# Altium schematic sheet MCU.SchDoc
size A4
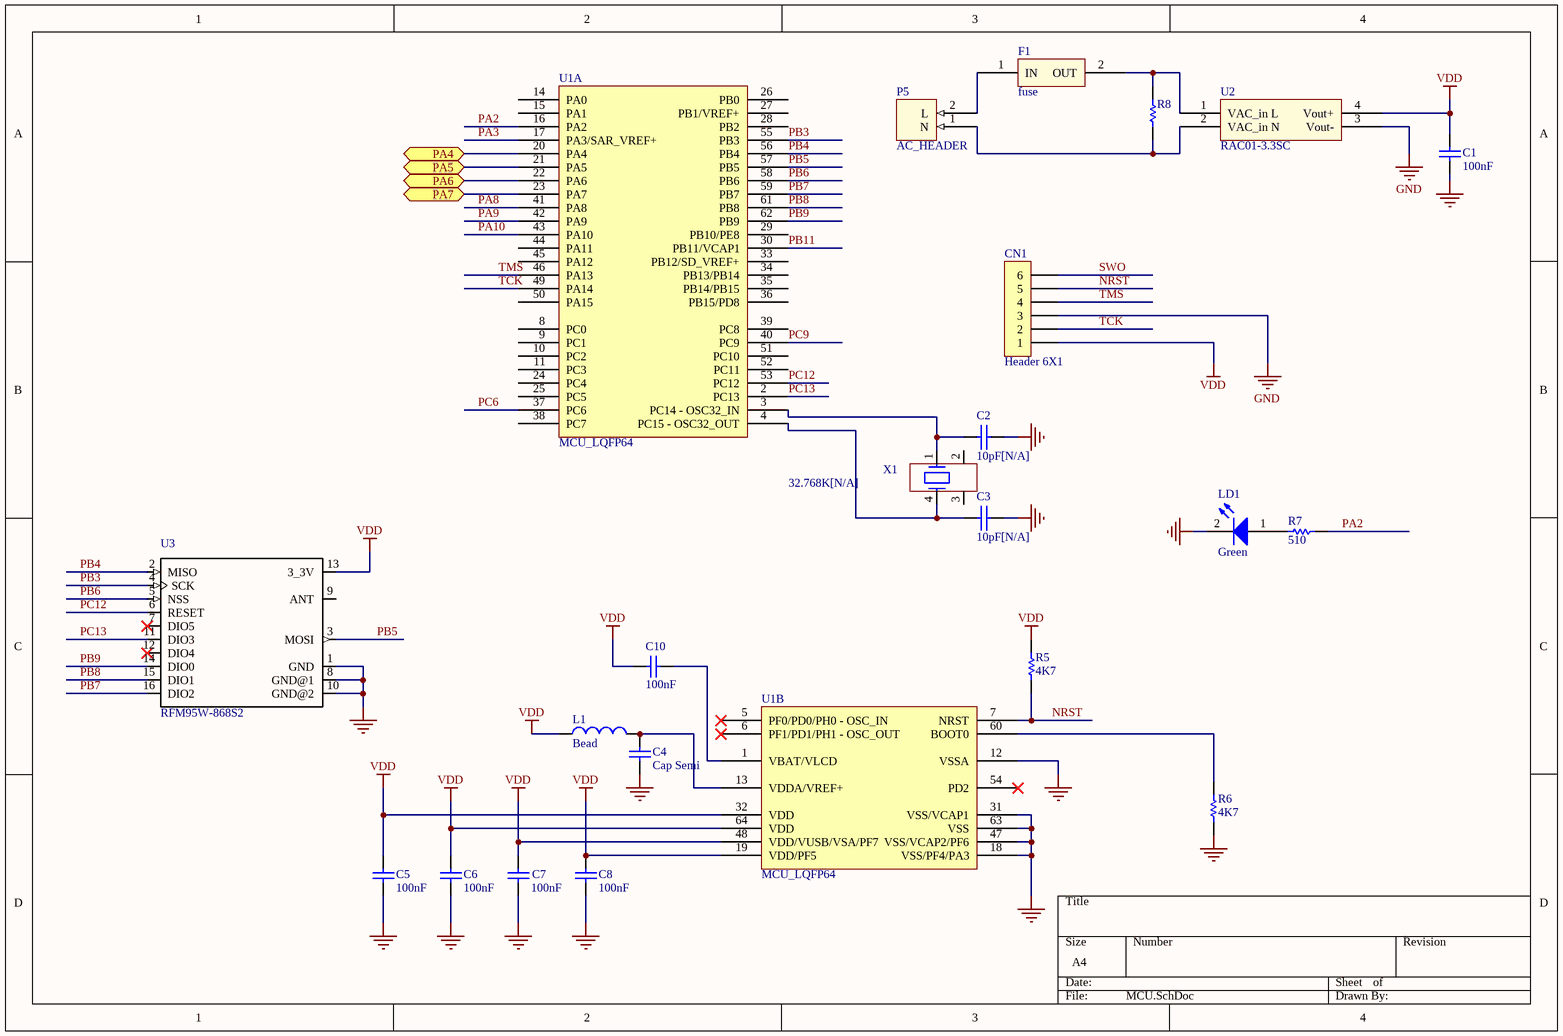
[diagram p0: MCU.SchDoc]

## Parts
C1  100nF  [0603C]
C2  10pF[N/A]  [0603C]
C3  10pF[N/A]  [0603C]
C4  Cap Semi  [1608[0603]]
C5  100nF  [0603C]
C6  100nF  [0603C]
C7  100nF  [0603C]
C8  100nF  [0603C]
C10  100nF  [0603C]
CN1  Header 6X1  [1*6P]
F1  fuse  [fuse]
L1  Bead  [INDC1608L]
LD1  Green  [0603D]
P5  AC_HEADER  [ac_header_2]
R5  4K7  [0603R]
R6  4K7  [0603R]
R7  510  [0603R]
R8  (no value)  [varistor]
U1  MCU_LQFP64  [LQFP64]  (parts A,B of 2)
U2  RAC01-3.3SC  [RAC01-3.3SC]
U3  RFM95W-868S2  [XCVR_RFM95W-868S2]
X1  32.768K[N/A]  [XTAL_4SM_8X3R8]

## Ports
PA4, PA5, PA6, PA7

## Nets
GND: C1.2 C2.2 C3.2 C4.2 C5.2 C6.2 C7.2 C8.2 CN1.3 LD1.2(K) R6.1 U1.12(VSSA) U1.18(VSS/PF4/PA3) U1.31(VSS/VCAP1) U1.47(VSS/VCAP2/PF6) U1.63(VSS) U2.3(Vout-) U3.1(GND) U3.8(GND@1) U3.10(GND@2)
VDD: C1.1 C5.1 C6.1 C7.1 C8.1 C10.1 CN1.1 L1.1 R5.2 U1.19(VDD/PF5) U1.32(VDD) U1.48(VDD/VUSB/VSA/PF7) U1.64(VDD) U2.4(Vout+) U3.13(3_3V)
NRST: CN1.5 R5.1 U1.7(NRST)
PA2: R7.1 U1.16(PA2)
PA3: U1.17(PA3/SAR_VREF+)
PA4: U1.20(PA4) ; port PA4
PA5: U1.21(PA5) ; port PA5
PA6: U1.22(PA6) ; port PA6
PA7: U1.23(PA7) ; port PA7
PA8: U1.41(PA8)
PA9: U1.42(PA9)
PA10: U1.43(PA10)
PB3: U1.55(PB3) U3.4(SCK)
PB4: U1.56(PB4) U3.2(MISO)
PB5: U1.57(PB5) U3.3(MOSI)
PB6: U1.58(PB6) U3.5(NSS)
PB7: U1.59(PB7) U3.16(DIO2)
PB8: U1.61(PB8) U3.15(DIO1)
PB9: U1.62(PB9) U3.14(DIO0)
PB11: U1.30(PB11/VCAP1)
PC6: U1.37(PC6)
PC9: U1.40(PC9)
PC12: U1.53(PC12) U3.6(RESET)
PC13: U1.2(PC13) U3.11(DIO3)
SWO: CN1.6
TCK: CN1.2 U1.49(PA14)
TMS: CN1.4 U1.46(PA13)
NetC2_1: C2.1 U1.3(PC14_-_OSC32_IN) X1.1
NetC3_1: C3.1 U1.4(PC15_-_OSC32_OUT) X1.4
NetC4_1: C4.1 L1.2 U1.13(VDDA/VREF+)
NetC10_2: C10.2 U1.1(VBAT/VLCD)
NetF1_1: F1.1(IN) P5.2(L)
NetF1_2: F1.2(OUT) R8.2 U2.1(VAC_in_L)
NetLD1_1: LD1.1(A) R7.2
NetP5_1: P5.1(N) R8.1 U2.2(VAC_in_N)
NetR6_2: R6.2 U1.60(BOOT0)

Not connected (* = marked no-connect by the designer): U1 5(PF0/PD0/PH0_-_OSC_IN)* 6(PF1/PD1/PH1_-_OSC_OUT)* 8(PC0) 9(PC1) 10(PC2) 11(PC3) 14(PA0) 15(PA1) 24(PC4) 25(PC5) 26(PB0) 27(PB1/VREF+) 28(PB2) 29(PB10/PE8) 33(PB12/SD_VREF+) 34(PB13/PB14) 35(PB14/PB15) 36(PB15/PD8) 38(PC7) 39(PC8) 44(PA11) 45(PA12) 50(PA15) 51(PC10) 52(PC11) 54(PD2)*; U3 7(DIO5)* 9(ANT) 12(DIO4)*; X1 2 3

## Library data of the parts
C1 = Cap: Capacitor; Manufacturer: AVX Corporation; Value: 0.1µF; ProductNumber: C1608X5R1H104K080AA; Vendor Name: Digikey; Vendor PN: 478-6206-1-ND
C2 = Cap: Capacitor; Manufacturer: Murata Electronics North America; ProductNumber: GRM1885C1H100JA01D; Value: 10pF; Vendor Name: Digikey; Vendor PN: 490-1403-1-ND
C3 = CAP: Capacitor; Manufacturer: Murata Electronics North America; ProductNumber: GRM1885C1H100JA01D; Vendor Name: Digikey
C4 = Cap Semi: Capacitor (Semiconductor SIM Model); Manufacturer: TDK; ProductNumber: C1608X5R1H104K080AA; Vendor Name: Digikey
C5-C8 = Cap: Capacitor; Manufacturer: TDK; ProductNumber: C1608X5R1H104K080AA; Vendor Name: Digikey
C10 = Cap: Capacitor; Manufacturer: AVX Corporation; Value: 0.1µF; ProductNumber: C1608X5R1H104K080AA; Vendor name: Digikey; Vendor PN: 478-6206-1-ND
CN1 = Header 6X1: Header, 6-Pin, Single row; Manufacturer: Molex; ProductNumber: 0022232061; Vendor Name: Digikey; Vendor PN: WM4204-ND
F1 = fuse: 240VAC 1A; Manufacturer: Bel Fuse Inc.; ProductNumber: RST 1-BULK; Value: 1A 250VAC; Vendor Name: Digikey; Vendor PN: 507-1176-ND
L1 = Inductor: Manufacturer: Taiyo Yuden; Code_IEC: 1005; Value: 600 OHM; ProductNumber: BK1608HS601-T; Vendor Name: Digikey; Vendor PN: 587-1874-1-ND
LD1 = LED2: Typical RED, GREEN, YELLOW, AMBER GaAs LED; Manufacturer: Lite-On; ProductNumber: LTST-C190KGKT; Value: 571nm; Vendor Name: Digikey; Vendor PN: 160-1435-1-ND
P5 = AC_HEADER: Manufacturer: On Shore Technology; ProductNumber: OSTTC022162; Vendor Name: Digikey; Vendor PN: ED2609-ND
R5 = Res1: Resistor; Manufacturer: Yageo; Value: 4.7 kOhms; ProductNumber: RC0603JR-074K7L; Vendor Name: Digikey; Vendor PN: 311-4.7KGRCT-ND
R6 = Res1: Resistor; Manufacturer: Yageo; ProductNumber: RC0603JR-074K7L; Vendor Name: Digikey
R7 = Res1: Resistor; Manufacturer: Rohm Semiconductor; Value: 510 Ohms; ProductNumber: ESR03EZPJ511; Vendor Name: Digikey; Vendor PN: RHM510DCT-ND
R8 = Res1: Resistor; Manufacturer: Epcos (TDK); Value: 360V 400A; ProductNumber: B72205S0231K101; Vendor Name: Digikey; Vendor PN: 495-6478-ND
U1 = MCU_LQFP64: Manufacturer: STM; ProductNumber: STM32L476RGT6; Vendor Name: Mouser; Vendor PN: 511-STM32L476RGT6
U2 = RAC01-3.3SC: AC/DC converter; Manufacturer: Recom Power; Vendor Name: Mouser; Vendor PN: 919-RAC01-3.3SC
U3 = RFM95W-868S2: Manufacturer: RF Solutions; MF: Hope Microelectronics; Vendor Name: Digikey; Vendor PN: RFM95W-868S2-ND
X1 = MC306: Vendor Name: Digikey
